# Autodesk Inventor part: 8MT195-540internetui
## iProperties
Created: 2009-10
Part Number: 8MT195-540internetui
Document SubType Name: Modeling
Designer: Darius
Author: Darius
Translation Standard: STEP AP203
File Name: 8MT195-540.STEP
Preprocessor: SolidWorks 2003240
Postprocessor: Build: 272, Release: 10 SP3a - Date: Thu 12/15/2005
Sent Units: MILLIMETERS
Uncertainty: 1e-05
